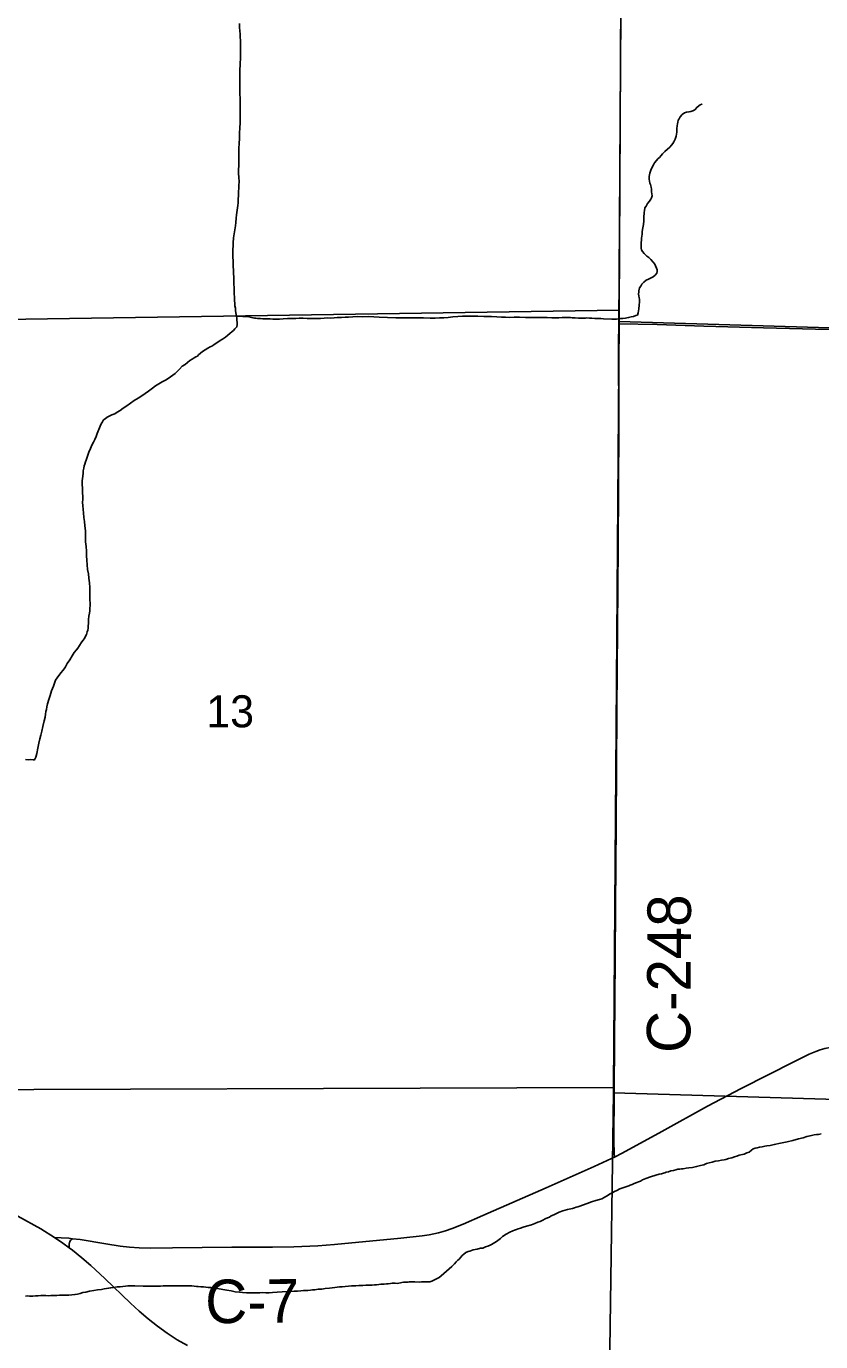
# Model space of a CAD drawing. Extents: x 1587405 to 1714697, y 1028970 to 1155083.
# Drawn here: x 1678758 to 1684232, y 1105868 to 1114934 of the extents above; entities that cross this region are included whole.
import ezdxf

# ---------------------------------------------------------------- set-up
doc = ezdxf.new("R2010")
doc.units = 0
for name, color, linetype in [('GM_X_County_Road', 7, 'Continuous'), ('GM_X_County_Road_Text', 7, 'Continuous'), ('GM_X_Minor_River', 7, 'Continuous'), ('GM_X_Section', 7, 'Continuous'), ('GM_X_Section_Text', 7, 'Continuous'), ('GM_X_State_Route', 7, 'Continuous'), ('GM_X_Township_Road', 7, 'Continuous')]:
    doc.layers.add(name, color=color, linetype=linetype)

msp = doc.modelspace()

# ---------------------------------------------------------------- linework, layer by layer
at = {"layer": 'GM_X_County_Road'}
for points in [[(1682840.3, 1112883.5), (1682843.5, 1113219.5), (1682849.1, 1113941.1), (1682854.6, 1115023.7), (1682858.4, 1115450.1), (1682860.3, 1116007.8), (1682861.2, 1116335.8), (1682866.9, 1116827.9), (1682869.2, 1117273)], [(1682810.9, 1107140), (1682810.1, 1107167), (1682807.6, 1107248.8), (1682812.3, 1107937.6), (1682815.9, 1108511.9), (1682818.6, 1108872.7), (1682822.4, 1109430.5), (1682828.5, 1110217.8), (1682836, 1111349.5), (1682841, 1112169.8), (1682839, 1112743.9), (1682840.3, 1112883.5)], [(1682810.9, 1107140), (1682863.8, 1107166.9), (1683136.8, 1107317.8), (1683453.3, 1107491.4), (1683685.4, 1107614), (1684051.4, 1107799.6), (1684154.2, 1107850.1), (1684199.3, 1107869.1), (1684230, 1107879.5), (1684261.4, 1107887.9), (1684309.3, 1107897.2), (1684358, 1107903.3), (1684439.5, 1107910.2), (1684865.4, 1107935.1), (1685078.6, 1107945), (1685275.1, 1107957.1), (1685635.7, 1107976.4), (1685979.9, 1107991.9), (1686783.3, 1108017.6), (1686983.3, 1108023.9)], [(1679075.6, 1106578.1), (1679128.9, 1106572.2), (1679306.8, 1106542.5), (1679404.2, 1106527), (1679469.6, 1106519.6), (1679535.2, 1106515.5), (1679617.3, 1106513.7), (1679765.2, 1106514.9), (1680175.3, 1106518.8), (1680454.2, 1106519.3), (1680602, 1106522.6), (1680766.1, 1106528.4), (1680880.9, 1106537), (1681338.2, 1106582.2), (1681485.3, 1106597.1), (1681534.1, 1106604.7), (1681598.6, 1106618.5), (1681646.3, 1106631.9), (1681693, 1106648), (1681769.5, 1106678.2), (1681905, 1106737.6), (1682340.7, 1106929), (1682671.1, 1107074.6), (1682790.5, 1107129.7), (1682810.9, 1107140)], [(1678953.1, 1106586.9), (1678998.2, 1106584.1), (1679050.3, 1106580.9), (1679075.6, 1106578.1)], [(1679054.4, 1106515.7), (1679054.7, 1106540.8), (1679055.9, 1106551.5), (1679057.2, 1106556.6), (1679061.9, 1106566.8), (1679075.6, 1106578.1)]]:
    msp.add_lwpolyline(points, dxfattribs=at)
at = {"layer": 'GM_X_Minor_River'}
for points in [[(1680225.4, 1114127.2), (1680227.9, 1114161.3), (1680228.3, 1114197.5), (1680230.8, 1114233.6), (1680231.3, 1114269.8), (1680231.7, 1114303.9), (1680232.1, 1114336.1), (1680232.5, 1114364.2), (1680232.9, 1114400.3), (1680231.3, 1114434.5), (1680229.8, 1114470.7), (1680230.3, 1114508.8), (1680228.7, 1114543), (1680229, 1114569.1), (1680229.4, 1114595.2), (1680229.7, 1114621.3), (1680232.5, 1114683.6), (1680234.9, 1114709.6), (1680235.2, 1114737.8), (1680233.5, 1114761.9), (1680233.7, 1114780), (1680233.9, 1114794), (1680234.1, 1114806.1), (1680234.2, 1114818.1), (1680234.5, 1114838.2), (1680232.7, 1114858.3), (1680231, 1114880.4), (1680229.3, 1114902.6), (1680227.6, 1114926.7), (1680227.9, 1114952.8)], [(1682957.6, 1112940.4), (1682969.8, 1112944.2), (1682974, 1112960.2), (1682978.4, 1112986.3), (1682980.7, 1113012.4), (1682983, 1113034.4), (1682983.2, 1113050.5), (1682981.4, 1113064.6), (1682979.5, 1113074.7), (1682977.7, 1113090.8), (1682979.8, 1113100.8), (1682979.9, 1113110.8), (1682984.2, 1113130.8), (1682992.4, 1113142.8), (1683000.7, 1113156.8), (1683012.9, 1113170.7), (1683029.2, 1113184.5), (1683045.4, 1113192.3), (1683059.6, 1113198.2), (1683077.9, 1113208), (1683092.1, 1113219.8), (1683102.4, 1113233.8), (1683104.5, 1113243.8), (1683104.7, 1113255.8), (1683089, 1113294.2), (1683077.1, 1113308.4), (1683061.3, 1113326.7), (1683047.3, 1113340.9), (1683035.4, 1113349.1), (1683025.4, 1113359.3), (1683015.5, 1113367.5), (1683003.6, 1113381.7), (1682997.7, 1113393.8), (1682995.8, 1113403.9), (1682996, 1113417.9), (1682996.1, 1113432), (1682996.3, 1113446.1), (1682996.5, 1113458.1), (1682998.7, 1113474.2), (1683001.1, 1113502.2), (1683003.3, 1113520.3), (1683007.6, 1113544.3), (1683012, 1113568.4), (1683014.3, 1113592.5), (1683014.6, 1113612.6), (1683014.7, 1113626.6), (1683014.9, 1113640.7), (1683017.1, 1113652.7), (1683017.2, 1113662.7), (1683021.5, 1113682.8), (1683029.7, 1113694.7), (1683040, 1113712.7), (1683052.3, 1113728.6), (1683062.5, 1113742.5), (1683066.7, 1113752.5), (1683070.9, 1113766.5), (1683069, 1113778.6), (1683067.2, 1113792.6), (1683065.4, 1113810.8), (1683063.6, 1113824.8), (1683059.8, 1113843), (1683055.9, 1113853.1), (1683052.1, 1113867.2), (1683050.2, 1113881.3), (1683050.5, 1113899.3), (1683054.8, 1113921.4), (1683061.1, 1113943.4), (1683071.4, 1113963.3), (1683079.7, 1113979.3), (1683087.9, 1113993.2), (1683112.5, 1114023.1), (1683122.6, 1114031), (1683132.9, 1114042.9), (1683143.1, 1114054.8), (1683157.4, 1114070.7), (1683175.7, 1114088.5), (1683192, 1114102.4), (1683204.3, 1114114.3), (1683212.5, 1114126.2), (1683220.7, 1114138.1), (1683229, 1114156.1), (1683237.3, 1114176.1), (1683239.5, 1114190.1), (1683241.7, 1114204.2), (1683241.9, 1114220.2), (1683242, 1114230.3), (1683244.3, 1114248.3), (1683246.4, 1114262.3), (1683248.6, 1114274.4), (1683250.8, 1114286.4), (1683257, 1114296.4), (1683263.2, 1114310.3), (1683277.5, 1114326.2), (1683293.7, 1114338.1), (1683307.9, 1114341.9), (1683324, 1114343.7), (1683338.2, 1114347.5), (1683350.3, 1114351.4), (1683364.5, 1114359.2), (1683380.9, 1114377.1), (1683401.2, 1114392.9)], [(1683401.2, 1114392.9), (1683413.4, 1114398.8), (1683415.4, 1114400.7)], [(1679404.3, 1112285.9), (1679426.6, 1112301.7), (1679451, 1112319.4), (1679475.4, 1112337.2), (1679501.8, 1112354.9), (1679528.2, 1112370.7), (1679554.6, 1112388.4), (1679577, 1112404.2), (1679599.3, 1112419.9), (1679627.8, 1112439.7), (1679648.1, 1112455.5), (1679670.5, 1112471.2), (1679694.8, 1112485), (1679717.1, 1112494.7), (1679735.4, 1112506.6), (1679751.7, 1112518.4), (1679767.9, 1112530.2), (1679784.2, 1112542.1), (1679798.5, 1112555.9), (1679814.8, 1112571.8), (1679833.2, 1112591.6), (1679853.5, 1112603.4), (1679869.8, 1112617.3), (1679886, 1112631.1), (1679900.3, 1112641), (1679914.5, 1112648.8), (1679926.7, 1112656.7), (1679936.8, 1112660.6), (1679945, 1112670.5), (1679959.2, 1112680.4), (1679973.4, 1112692.2), (1679989.7, 1112704.1), (1680010, 1112715.9), (1680024.2, 1112725.7), (1680036.4, 1112729.6), (1680050.6, 1112739.5), (1680093.3, 1112769), (1680109.5, 1112778.9), (1680129.8, 1112790.6), (1680148.1, 1112804.5), (1680160.3, 1112816.4), (1680176.6, 1112830.2), (1680186.8, 1112838.1), (1680195, 1112848.1), (1680209.2, 1112861.9), (1680211.5, 1112880), (1680211.7, 1112896), (1680209.8, 1112906.1), (1680208, 1112922.2), (1680206.2, 1112936.3), (1680204.3, 1112948.4), (1680202.5, 1112960.4), (1680200.6, 1112974.5), (1680198.8, 1112990.6), (1680195, 1113006.7), (1680195.2, 1113024.8), (1680193.5, 1113044.9), (1680191.8, 1113069.1), (1680190, 1113089.2), (1680190.3, 1113109.2), (1680190.6, 1113133.3), (1680188.8, 1113157.5), (1680189.1, 1113179.6), (1680187.4, 1113203.7), (1680185.8, 1113233.9), (1680186.1, 1113255.9), (1680184.3, 1113276.1), (1680184.6, 1113298.1), (1680182.9, 1113320.3), (1680181.1, 1113340.4), (1680181.3, 1113358.5), (1680181.6, 1113380.5), (1680181.9, 1113398.6), (1680184.1, 1113418.7), (1680184.4, 1113442.8), (1680186.9, 1113476.9), (1680191.2, 1113503), (1680195.6, 1113531), (1680200, 1113559.1), (1680202.3, 1113583.2), (1680204.7, 1113611.2), (1680207, 1113635.3), (1680213.7, 1113683.4), (1680215.9, 1113699.5), (1680218.2, 1113717.5), (1680218.5, 1113745.7), (1680220.8, 1113765.7), (1680221, 1113781.8), (1680221.2, 1113797.8), (1680223.4, 1113815.9), (1680223.7, 1113838), (1680224.1, 1113864.1), (1680222.4, 1113892.2), (1680220.8, 1113922.4), (1680221.1, 1113948.5), (1680223.4, 1113972.6), (1680223.9, 1114006.7), (1680222.2, 1114034.9), (1680222.6, 1114065), (1680223, 1114095.1), (1680225.4, 1114127.2)], [(1680206.2, 1112936.3), (1680290.7, 1112931.2), (1680310.8, 1112926.9), (1680320.8, 1112924.7), (1680330.9, 1112922.6), (1680341, 1112922.5), (1680353, 1112920.3), (1680371.1, 1112920.1), (1680387.2, 1112917.8), (1680403.3, 1112917.6), (1680419.4, 1112917.4), (1680439.6, 1112917.1), (1680457.7, 1112916.9), (1680475.8, 1112916.7), (1680502, 1112916.3), (1680528.2, 1112918), (1680558.4, 1112919.6), (1680588.7, 1112921.2), (1680614.9, 1112920.9), (1680639, 1112922.6), (1680667.2, 1112922.2), (1680693.4, 1112919.8), (1680713.5, 1112919.6), (1680731.7, 1112919.3), (1680753.8, 1112921.1), (1680786.1, 1112920.6), (1680810.3, 1112922.3), (1680832.4, 1112924.1), (1680854.6, 1112923.8), (1680878.8, 1112925.4), (1680901, 1112927.2), (1680929.2, 1112926.8), (1680955.4, 1112928.5), (1680979.5, 1112930.2), (1681007.8, 1112931.8), (1681040, 1112933.4), (1681072.2, 1112933), (1681116.6, 1112934.4), (1681152.8, 1112931.9), (1681189, 1112929.4), (1681305.8, 1112925.9), (1681342.1, 1112925.4), (1681380.3, 1112924.9), (1681418.6, 1112924.4), (1681458.9, 1112925.9), (1681495.1, 1112925.4), (1681541.4, 1112922.8), (1681575.7, 1112922.3), (1681605.9, 1112923.9), (1681636.1, 1112925.6), (1681666.4, 1112927.2), (1681698.6, 1112930.8), (1681730.9, 1112934.4), (1681765.2, 1112935.9), (1681799.4, 1112935.5), (1681831.6, 1112937.1), (1681869.9, 1112936.6), (1681912.2, 1112934), (1681964.5, 1112933.3), (1682000.8, 1112930.8), (1682033, 1112930.4), (1682061.2, 1112930), (1682091.4, 1112927.6), (1682119.6, 1112929.3), (1682155.8, 1112928.8), (1682198.1, 1112928.2), (1682236.4, 1112927.7), (1682270.6, 1112927.3), (1682302.8, 1112926.9), (1682347.2, 1112926.3), (1682379.4, 1112925.9), (1682405.6, 1112925.5), (1682427.7, 1112925.2), (1682449.9, 1112926.9), (1682470, 1112926.7), (1682490.2, 1112926.4), (1682508.3, 1112926.2), (1682520.4, 1112926), (1682540.5, 1112925.8), (1682564.6, 1112923.4), (1682586.8, 1112923.1), (1682611, 1112922.8), (1682621.1, 1112924.7), (1682639.2, 1112922.4), (1682655.3, 1112922.2), (1682675.4, 1112920), (1682697.5, 1112919.7), (1682717.7, 1112919.4), (1682735.8, 1112919.2), (1682792.2, 1112916.4), (1682808.3, 1112916.2), (1682826.4, 1112916), (1682840.5, 1112917.8), (1682852.6, 1112919.6), (1682868.8, 1112921.4), (1682886.9, 1112923.2), (1682897, 1112925.1), (1682909.1, 1112926.9), (1682927.3, 1112932.7), (1682941.4, 1112934.6), (1682957.6, 1112940.4)], [(1678873, 1110107.2), (1678881.6, 1110147.3), (1678888, 1110173.3), (1678890.2, 1110193.4), (1678892.5, 1110211.4), (1678896.7, 1110225.4), (1678898.9, 1110243.5), (1678905.2, 1110265.5), (1678913.7, 1110293.5), (1678922.1, 1110321.5), (1678932.5, 1110353.5), (1678945, 1110385.5), (1678959.7, 1110427.5), (1678982.2, 1110459.3), (1678998.6, 1110481.2), (1679010.9, 1110495.1), (1679019.1, 1110505.1), (1679027.3, 1110519), (1679039.7, 1110543), (1679058.2, 1110568.8), (1679074.6, 1110594.7), (1679089, 1110618.7), (1679103.3, 1110636.6), (1679113.5, 1110648.5), (1679125.9, 1110666.4), (1679136.2, 1110684.3), (1679148.4, 1110700.2), (1679158.7, 1110714.2), (1679167, 1110730.1), (1679173.1, 1110742.1), (1679177.4, 1110760.1), (1679181.6, 1110772.1), (1679183.8, 1110786.2), (1679184, 1110802.2), (1679186.2, 1110818.3), (1679186.6, 1110846.4), (1679188.9, 1110868.5), (1679193.1, 1110888.5), (1679195.4, 1110904.5), (1679195.6, 1110924.6), (1679197.9, 1110942.7), (1679196.5, 1110996.9), (1679196.8, 1111019), (1679197.1, 1111041.1), (1679195.4, 1111065.2), (1679193.8, 1111099.4), (1679190.2, 1111129.6), (1679186.5, 1111159.8), (1679180.8, 1111190), (1679177.2, 1111222.2), (1679175.6, 1111254.3), (1679174, 1111284.5), (1679172.4, 1111316.7), (1679170.8, 1111348.8), (1679167.2, 1111381), (1679165.6, 1111413.2), (1679166.1, 1111457.4), (1679162.5, 1111491.6), (1679158.9, 1111521.7), (1679155.2, 1111549.9), (1679151.6, 1111580.1), (1679149.9, 1111604.2), (1679148.2, 1111630.4), (1679146.4, 1111652.5), (1679146.7, 1111674.6), (1679147, 1111696.7), (1679145.3, 1111716.8), (1679145.5, 1111732.9), (1679145.7, 1111754.9), (1679143.9, 1111771), (1679144.1, 1111785.1), (1679144.3, 1111801.2), (1679146.5, 1111817.2), (1679146.7, 1111833.3), (1679149, 1111853.3), (1679151.2, 1111871.4), (1679153.5, 1111889.4), (1679157.7, 1111905.5), (1679161.9, 1111917.4), (1679166.1, 1111933.5), (1679170.3, 1111943.5), (1679176.6, 1111963.5), (1679182.8, 1111979.4), (1679189.1, 1111999.5), (1679199.5, 1112023.4), (1679209.9, 1112047.4), (1679220.2, 1112067.3), (1679230.5, 1112087.3), (1679238.8, 1112107.3), (1679247.2, 1112127.3), (1679268, 1112179.2), (1679274.2, 1112195.2), (1679282.4, 1112209.2), (1679290.7, 1112221.1), (1679300.8, 1112229), (1679315.1, 1112240.9), (1679329.2, 1112246.7), (1679347.5, 1112256.5), (1679367.7, 1112264.3), (1679384, 1112274.1), (1679404.3, 1112285.9)], [(1678753.3, 1109879.8), (1678771.4, 1109879.5), (1678789.6, 1109881.3), (1678805.7, 1109879.1), (1678815.7, 1109878.9), (1678824, 1109896.9), (1678830.4, 1109922.9), (1678836.9, 1109959), (1678845.4, 1109993.1), (1678851.8, 1110023.1), (1678858.2, 1110049.2), (1678864.6, 1110075.2), (1678873, 1110107.2)], [(1682411.8, 1106752), (1682430.1, 1106761.8), (1682454.4, 1106769.5), (1682470.5, 1106775.3), (1682488.7, 1106779.1), (1682498.8, 1106781), (1682510.9, 1106784.9), (1682523.1, 1106786.7), (1682535.2, 1106790.6), (1682547.3, 1106794.4), (1682559.5, 1106798.3), (1682573.6, 1106802.1), (1682591.8, 1106809.9), (1682624.2, 1106819.5), (1682652.5, 1106831.2), (1682682.9, 1106840.9), (1682707.1, 1106848.6), (1682723.3, 1106852.4), (1682739.5, 1106862.2), (1682751.7, 1106868.1), (1682761.8, 1106874), (1682776.1, 1106885.8), (1682800.4, 1106895.6), (1682812.6, 1106903.5), (1682828.7, 1106909.3), (1682849, 1106921.1), (1682869.3, 1106928.8), (1682895.6, 1106938.5), (1682909.7, 1106942.4), (1682919.9, 1106946.2), (1682934, 1106952.1), (1682946.2, 1106957.9), (1682964.4, 1106965.8), (1682976.5, 1106969.6), (1682990.7, 1106975.4), (1683004.9, 1106983.3), (1683027.2, 1106993.1), (1683059.6, 1107004.7), (1683096, 1107016.2), (1683120.2, 1107022), (1683134.4, 1107025.8), (1683148.5, 1107029.6), (1683158.6, 1107031.5), (1683168.7, 1107035.4), (1683182.9, 1107039.2), (1683199.1, 1107045), (1683217.2, 1107048.8), (1683233.4, 1107052.6), (1683247.5, 1107056.5), (1683261.7, 1107058.3), (1683273.8, 1107060.1), (1683285.9, 1107060), (1683306, 1107063.7), (1683324.2, 1107065.5), (1683348.4, 1107069.2), (1683376.7, 1107074.9), (1683405, 1107082.5), (1683427.2, 1107088.2), (1683445.4, 1107096.1), (1683463.6, 1107099.8), (1683483.8, 1107105.6), (1683506.1, 1107111.3), (1683528.3, 1107115.1), (1683548.4, 1107118.8), (1683566.6, 1107120.6), (1683578.7, 1107124.4), (1683596.9, 1107130.2), (1683619.2, 1107136), (1683639.4, 1107141.7), (1683653.5, 1107147.6), (1683669.7, 1107153.4), (1683704.1, 1107161), (1683714.2, 1107164.8), (1683724.3, 1107168.7), (1683740.5, 1107174.5), (1683754.8, 1107188.4), (1683767, 1107196.3), (1683781.1, 1107202.1), (1683795.3, 1107204), (1683811.4, 1107207.8), (1683829.6, 1107211.6), (1683847.8, 1107215.3), (1683861.9, 1107217.2), (1683884.1, 1107220.9), (1683912.4, 1107226.5), (1683954.8, 1107236), (1684001.2, 1107245.5), (1684041.6, 1107255), (1684080, 1107266.5), (1684112.4, 1107274.1), (1684136.6, 1107281.8), (1684158.9, 1107287.6), (1684187.1, 1107293.2), (1684203.3, 1107295.1), (1684217.4, 1107296.9), (1684235.6, 1107300.6)], [(1680683, 1106220.2), (1680699.1, 1106222), (1680717.3, 1106223.8), (1680731.4, 1106225.6), (1680747.5, 1106225.4), (1680769.7, 1106229.1), (1680793.9, 1106230.8), (1680818.1, 1106234.5), (1680848.4, 1106238.1), (1680884.7, 1106241.7), (1680916.9, 1106245.3), (1680935.1, 1106247), (1680955.2, 1106248.8), (1680977.4, 1106250.5), (1680999.6, 1106252.2), (1681015.7, 1106252), (1681029.8, 1106253.8), (1681050, 1106255.6), (1681076.2, 1106255.2), (1681098.4, 1106256.9), (1681116.5, 1106258.7), (1681140.7, 1106258.4), (1681156.8, 1106260.2), (1681170.9, 1106260), (1681187.1, 1106261.8), (1681201.2, 1106263.6), (1681213.3, 1106263.5), (1681225.4, 1106265.3), (1681239.5, 1106267.1), (1681251.6, 1106267), (1681267.7, 1106268.8), (1681279.8, 1106270.6), (1681300, 1106270.4), (1681316.1, 1106270.2), (1681326.2, 1106272), (1681336.3, 1106273.9), (1681346.3, 1106275.8), (1681358.5, 1106277.6), (1681374.6, 1106279.4), (1681388.7, 1106279.2), (1681398.8, 1106281.1), (1681414.9, 1106280.9), (1681435, 1106280.7), (1681465.2, 1106278.2), (1681481.3, 1106280.1), (1681493.4, 1106279.9), (1681505.5, 1106279.7), (1681523.7, 1106281.5), (1681539.8, 1106281.3), (1681551.9, 1106285.1), (1681566.1, 1106291), (1681576.2, 1106296.9), (1681588.4, 1106302.7), (1681602.6, 1106310.6), (1681616.8, 1106322.5), (1681635.2, 1106338.3), (1681653.5, 1106354.1), (1681671.8, 1106370), (1681690.2, 1106385.8), (1681708.5, 1106403.6), (1681720.8, 1106417.5), (1681731, 1106429.5), (1681741.2, 1106437.3), (1681753.4, 1106451.3), (1681761.6, 1106461.2), (1681773.8, 1106471.1), (1681788.1, 1106482.9), (1681804.3, 1106490.8), (1681814.4, 1106492.6), (1681838.6, 1106500.4), (1681864.9, 1106506.1), (1681889.1, 1106511.8), (1681905.3, 1106513.6), (1681921.5, 1106521.4), (1681939.7, 1106527.2), (1681953.9, 1106533), (1681964, 1106538.9), (1681986.3, 1106552.7), (1681998.5, 1106558.5), (1682025, 1106580.3), (1682039.2, 1106594.2), (1682065.6, 1106609.9), (1682090, 1106623.6), (1682110.2, 1106631.4), (1682122.4, 1106637.3), (1682136.5, 1106641.1), (1682148.7, 1106647), (1682164.8, 1106650.8), (1682183, 1106656.6), (1682205.3, 1106664.3), (1682239.6, 1106673.9), (1682261.9, 1106681.6), (1682282.2, 1106691.4), (1682300.4, 1106697.2), (1682316.6, 1106705), (1682334.8, 1106714.8), (1682349, 1106720.7), (1682363.2, 1106726.5), (1682375.4, 1106734.4), (1682393.6, 1106742.2), (1682411.8, 1106752)], [(1678752.8, 1106181.3), (1678767, 1106183.1), (1678781.1, 1106182.9), (1678803.2, 1106182.6), (1678821.4, 1106184.4), (1678839.5, 1106184.1), (1678857.6, 1106185.9), (1678875.8, 1106185.7), (1678893.9, 1106185.4), (1678912, 1106185.2), (1678928.2, 1106187), (1678948.3, 1106186.7), (1678968.4, 1106186.5), (1678986.6, 1106188.2), (1679004.7, 1106188), (1679030.9, 1106189.7), (1679051.1, 1106189.4), (1679071.2, 1106191.1), (1679093.4, 1106192.9), (1679111.6, 1106196.6), (1679129.7, 1106200.4), (1679147.9, 1106206.2), (1679168.1, 1106210), (1679194.4, 1106215.6), (1679224.7, 1106221.3), (1679248.9, 1106225), (1679277.1, 1106228.6), (1679295.3, 1106232.4), (1679311.5, 1106234.2), (1679325.6, 1106236), (1679339.7, 1106239.8), (1679359.9, 1106241.6), (1679384.1, 1106245.3), (1679404.3, 1106247), (1679442.6, 1106250.6), (1679458.7, 1106252.3), (1679476.8, 1106252.1), (1679505.1, 1106253.8), (1679563.4, 1106251), (1679577.5, 1106250.8), (1679593.7, 1106250.6), (1679611.8, 1106250.3), (1679629.9, 1106250.1), (1679650.1, 1106251.8), (1679666.2, 1106251.6), (1679682.3, 1106251.4), (1679700.4, 1106253.2), (1679718.6, 1106252.9), (1679736.7, 1106252.7), (1679754.8, 1106252.5), (1679775, 1106254.2), (1679795.1, 1106254), (1679817.3, 1106253.7), (1679837.4, 1106253.4), (1679853.5, 1106253.2), (1679867.6, 1106253), (1679879.7, 1106252.8), (1679897.8, 1106252.6), (1679915.9, 1106250.4), (1679930, 1106248.2), (1679942.1, 1106248), (1679960.2, 1106245.8), (1679980.3, 1106245.5), (1679996.4, 1106243.3), (1680012.5, 1106241.1), (1680030.6, 1106240.8), (1680050.7, 1106236.5), (1680076.9, 1106234.2), (1680113, 1106227.7), (1680139.2, 1106223.3), (1680169.3, 1106218.9), (1680197.4, 1106212.5), (1680227.6, 1106210.1), (1680247.7, 1106207.8), (1680275.9, 1106205.5), (1680296, 1106205.2), (1680316.2, 1106204.9), (1680338.3, 1106204.6), (1680366.5, 1106204.3), (1680386.7, 1106206), (1680408.9, 1106205.7), (1680431, 1106205.4), (1680455.2, 1106207.1), (1680487.4, 1106208.7), (1680521.7, 1106212.3), (1680604.4, 1106215.2), (1680626.5, 1106216.9), (1680650.7, 1106218.6), (1680668.9, 1106220.4), (1680683, 1106220.2)]]:
    msp.add_lwpolyline(points, dxfattribs=at)
at = {"layer": 'GM_X_Section'}
for points in [[(1677623.6, 1118159.2), (1682873.4, 1118189.7), (1682870.9, 1118149.7), (1682843.6, 1112977.4), (1677539.9, 1112896.8)], [(1682870.9, 1118149.7), (1688556.8, 1118001), (1688414.9, 1112733.1), (1682843.2, 1112899.7), (1682843.6, 1112977.4)], [(1682843.6, 1112977.4), (1682843.2, 1112899.7), (1682805.3, 1107619.6), (1677475.7, 1107602.1), (1677539.9, 1112896.8)], [(1688414.9, 1112733.1), (1688276.4, 1107421.2), (1682804.9, 1107583.5), (1682805.3, 1107619.6), (1682843.2, 1112899.7)], [(1677475.7, 1107602.1), (1682805.3, 1107619.6), (1682804.9, 1107583.5), (1682728.6, 1102289), (1677347.9, 1102346.3)], [(1682804.9, 1107583.5), (1688276.4, 1107421.2), (1688124.2, 1102135.5), (1682728.6, 1102289)]]:
    msp.add_lwpolyline(points, close=True, dxfattribs=at)
at = {"layer": 'GM_X_State_Route'}
msp.add_lwpolyline([(1678700.3, 1106733.1), (1678857.9, 1106644.8), (1678953.1, 1106586.9), (1679010.8, 1106548.2), (1679054.4, 1106515.7), (1679076.8, 1106499.1), (1679140.5, 1106447.1), (1679202.3, 1106392.9), (1679298.3, 1106303.2), (1679475.7, 1106132.6), (1679536.4, 1106077.6), (1679598.9, 1106024.8), (1679663.3, 1105974.3), (1679729.8, 1105926.6), (1679798.4, 1105882), (1679869, 1105840.8)], dxfattribs=at)
at = {"layer": 'GM_X_Township_Road'}
msp.add_lwpolyline([(1684693.9, 1112835.9), (1684196, 1112847.9), (1683839.2, 1112855.7), (1683428, 1112867.8), (1683104.5, 1112879), (1682840.3, 1112883.5)], dxfattribs=at)

# ---------------------------------------------------------------- texts
at = {"layer": 'GM_X_County_Road_Text'}
for s, rotation, p in [('C-248', 89.72398, (1683333.9, 1107857.7)), ('C-7', 0.4581, (1679992.1, 1105994.9))]:
    msp.add_text(s, height=300, rotation=rotation, dxfattribs=at).set_placement(p)
at = {"layer": 'GM_X_Section_Text'}
msp.add_text('13', height=221, rotation=0.00001, dxfattribs=at).set_placement((1679998.9, 1110102.4))

doc.saveas('drawing.dxf')
